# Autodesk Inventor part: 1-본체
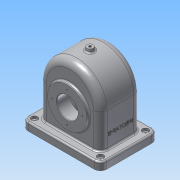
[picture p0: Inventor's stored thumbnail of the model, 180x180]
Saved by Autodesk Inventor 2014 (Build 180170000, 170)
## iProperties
Created: 2016-10
Part Number: 1-본체
Material: Aluminum 6061
Document SubType Name: Modeling
Designer: user
Mass: 1216.28 g
Surface Area: 1195.85 cm^2
Volume: 448.811 cm^3
Density: 2.71 g/cm^3
Appearance: Aluminum - Flat
Author: user
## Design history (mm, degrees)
sketch "Sketch1"
  geometry: L1 (-58, 0)-(58, 0); L2 (58, 0)-(58, 80); L3 (-58, 80)-(-58, 0); A1 r 58 centre (0, 80) between (58, 80) and (-58, 80); 2 further points
  constraints: 6 end point, 2 point on circle, 2 tangent, 1 centre point, 1 coincident, 1 horizontal, 1 midpoint, 1 parallel, 1 perpendicular
  dimensions: "d0" = 58 radius of A1; "d1" = 80 distance from line of L1 A1.centre
extrude "Extrusion1" new body sketch "Sketch1" stored distance "d2" = 77; taper "d3" = 0 deg
shell "Shell1" dims "d4" = 6
sketch "Sketch3"
  geometry: L1 (110, -71)-(6, -71) reference; L2 (6, -71)-(6, -6) reference; L3 (6, -6)-(110, -6) reference; L4 (110, -6)-(110, -71) reference; L5 (-5, 16.5)-(121, 16.5); L6 (133, 4.5)-(133, -81.5); L7 (121, -93.5)-(-5, -93.5); L8 (-17, -81.5)-(-17, 4.5); A1 r 12 centre (121, -81.5) between (121, -93.5) and (133, -81.5); A2 r 12 centre (121, 4.5) between (133, 4.5) and (121, 16.5); A3 r 12 centre (-5, 4.5) between (-5, 16.5) and (-17, 4.5); A4 r 12 centre (-5, -81.5) between (-17, -81.5) and (-5, -93.5); 6 further points
  constraints: 8 end point, 8 point on circle, 8 tangent, 6 point on line, 4 centre point, 3 equal radius, 2 midpoint, 2 parallel, 1 horizontal, 1 horizontal alignment, 1 perpendicular, 1 vertical alignment
  dimensions: "d5" = 150 distance of point (-17, 16.5) point (133, 16.5); "d6" = 110 distance of point (-17, -93.5) point (-17, 16.5); "d7" = 12 radius of A1
extrude "Extrusion2" join sketch "Sketch3" distance "d8" = 15; taper "d9" = 0 deg
sketch "Sketch4"
  geometry: L1 (-38.5, 65)-(38.5, 65); L2 (-38.5, 80)-(-38.5, 15) reference; L3 (38.5, 15)-(38.5, 80) reference; L4 (32.5, 0)-(-32.5, 0) reference; L5 (-32.5, 132)-(-32.5, 0) reference; L6 (-32.5, 0)-(-55, 0) reference; L7 (-55, 0)-(-55, 15) reference; L8 (-55, 15)-(-38.5, 15) reference; L9 (-38.5, 15)-(-38.5, 138) reference; L10 (-38.5, 138)-(38.5, 138) reference; L11 (38.5, 138)-(38.5, 15) reference; L12 (38.5, 15)-(55, 15) reference; L13 (55, 15)-(55, 0) reference; L14 (55, 0)-(32.5, 0) reference; L15 (32.5, 0)-(32.5, 132) reference; L16 (32.5, 132)-(-32.5, 132) reference; L17 (-32.5, 132)-(-32.5, 80) reference; L18 (-32.5, 103.908)-(-19.5, 93); L19 (-19.5, 93)-(-19.5, 65); L20 (-19.5, 65)-(-32.5, 65); L21 (-32.5, 80)-(-32.5, 0) reference; L22 (-32.5, 103.908)-(-32.5, 65); L23 (-38.5, 138)-(-38.5, 80) reference; L24 (-38.5, 102.5)-(-43.5, 102.5); L25 (-43.5, 102.5)-(-43.5, 65); L26 (-43.5, 65)-(-38.5, 65); L27 (-38.5, 65)-(-38.5, 102.5); 1 further point
  constraints: 18 end point, 7 point on line, 4 perpendicular, 2 parallel, 1 horizontal
  dimensions: "d10" = 65 distance between parallel lines of L4 L1; "d11" = 56 diameter of L18.end L1; "d12" = 50 deg angle of L19 L18; "d13" = 5 distance of L24.start L24.end; "d14" = 24 distance between parallel lines of L19 L25; "d15" = 75 diameter of L24 L1
revolve "Revolution1" sketch "Sketch4" stored, may be unused: angle "d16" = 90 deg
sketch "Sketch5"
  geometry: L1 (-63, 0)-(63, 0) reference; C1 r 31 at (0, -65); A1 r 58 centre (0, -80) between (-58, -80) and (58, -80) reference; 1 further point
  constraints: 1 centre point, 1 vertical alignment
  dimensions: "d17" = 65 distance from line of L1 C1.centre; "d18" = 62 diameter of C1
extrude "Extrusion3" join sketch "Sketch5" distance "d19" = 10; taper "d20" = 0 deg
sketch "Sketch6"
  geometry: C1 r 37.5 at (0, 0) reference; 2 further points
  constraints: 1 coincident
hole "Hole1" sketch "Sketch6" at (0, 0) diameter "d21" = 40; stored, may be unused: countersink angle "d25" = 90 deg, drill point angle "d27" = 118 deg; dims "d22" = 6, "d23" = 4, "d24" = 2, "d26" = 8
sketch "Sketch7"
  geometry: C1 r 20 at (0, 0) reference; C2 r 37.5 at (0, 0) reference; 5 further points
  constraints: 1 vertical alignment, 5 other
  dimensions: "d28" = 29 distance of C1.centre point (0, 29); "d31" = 360 deg dimension on C2.centre point (0, 29) (derived)
hole "Hole2" sketch "Sketch7" at (0, 29), (-29, 0), (0, -29), (29, 0) diameter "d33" = 2.459; stored, may be unused: countersink angle "d37" = 90 deg, drill point angle "d39" = 118 deg; dims "d34" = 6, "d35" = 4, "d36" = 2, "d38" = 8
sketch "Sketch8"
  geometry: C1 r 20 at (0, 0) reference; C2 r 31 at (0, 0) reference; 5 further points
  constraints: 1 vertical alignment, 5 other
  dimensions: "d40" = 26 distance of C1.centre point (0, 26); "d43" = 360 deg dimension on C2.centre point (0, 26) (derived)
hole "Hole3" sketch "Sketch8" at (0, 26), (-26, 0), (0, -26), (26, 0) diameter "d45" = 2.459; stored, may be unused: countersink angle "d49" = 90 deg, drill point angle "d51" = 118 deg; dims "d46" = 6, "d47" = 4, "d48" = 2, "d50" = 8
sketch "Sketch9"
  geometry: A1 r 12 centre (-121, -81.5) between (-133, -81.5) and (-121, -93.5) reference; A2 r 12 centre (5, -81.5) between (5, -93.5) and (17, -81.5) reference; A3 r 12 centre (5, 4.5) between (17, 4.5) and (5, 16.5) reference; A4 r 12 centre (-121, 4.5) between (-121, 16.5) and (-133, 4.5) reference; 1 further point
hole "Hole4" sketch "Sketch9" at (5, -81.5), (-121, -81.5), (5, 4.5), (-121, 4.5) diameter "d52" = 5; stored, may be unused: countersink angle "d56" = 90 deg, drill point angle "d58" = 118 deg; dims "d53" = 6, "d54" = 12, "d55" = 5, "d57" = 20
workplane "Work Plane1"
sketch "Sketch15"
  geometry: C1 r 6 at (0, 0); 1 further point
  constraints: 1 centre point, 1 coincident
  dimensions: "d81" = 12 diameter of C1
extrude "Extrusion5" join sketch "Sketch15" stored distance "d82" = 10; taper "d83" = 10 deg
sketch "Sketch16"
  geometry: C1 r 6 at (0, 0) reference
hole "Hole6" sketch "Sketch16" at (0, 0) diameter "d84" = 4.459; stored, may be unused: countersink angle "d88" = 90 deg, drill point angle "d90" = 118 deg; dims "d85" = 20, "d86" = 12, "d87" = 5, "d89" = 20
chamfer "Chamfer1" distance "d69" = 1; stored, may be unused: second distance "d70" = 2, angle "d71" = 45 deg
fillet "Fillet1" dims "d72" = 13, "d73" = 8
fillet "Fillet2" dims "d74" = 3
workplane "Work Plane2"
sketch "Sketch13"
  geometry: L1 (80, 68.5)-(80, -17.5) reference; L2 (0, -13)-(62, -13) reference; 3 further points
  constraints: 1 other
  dimensions: "d76" = 40 distance from line of L1 point (40, 25.5); "d77" = 38.5 distance from line of point (40, 25.5) L2
emboss "Emboss1" sketch "Sketch13" dims "d0" = 58, "d1" = 80, "d5" = 150, "d6" = 110, "d7" = 12, "d79" = 0.5, "d80" = 0
body "Solid1"
node "Project Cut Edges1"
other parameters: "d59" = 144, "d75" = 3
